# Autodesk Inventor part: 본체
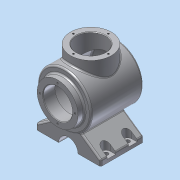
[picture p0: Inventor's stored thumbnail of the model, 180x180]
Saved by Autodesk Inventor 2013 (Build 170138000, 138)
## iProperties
Created: 2017-04
Part Number: 본체
Material: 알루미늄 6061
Document SubType Name: Modeling
Designer: narae
Density: 2.71 g/cm^3
Mass: 1670.76 g
Surface Area: 1066.88 cm^2
Volume: 616.516 cm^3
Author: narae
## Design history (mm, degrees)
sketch "스케치1"
  geometry: L1 (-50, 0)-(58, 0); L2 (-50, 0)-(-50, 50); L3 (-50, 50)-(46.336, 50); A1 r 113 centre (-55, 0) between (58, 0) and (46.336, 50); 2 further points
  constraints: 6 end point, 2 horizontal alignment, 2 perpendicular, 2 point on circle, 1 centre point, 1 horizontal, 1 midpoint, 1 point on line
  dimensions: "d0" = 108 distance of L1.end L1.start; "d1" = 50 distance of point (0, 0) L1.start; "d2" = 100 diameter of L3 L1; "d3" = 113 radius of A1
revolve "회전1" sketch "스케치1" stored, may be unused: angle "d4" = 90 deg
feature "쉘1" dims "d5" = 10
sketch "스케치2"
  geometry: C1 r 50 at (0, 0) reference; C2 r 38 at (0, 0)
  constraints: 1 centre point, 1 coincident
  dimensions: "d6" = 76 diameter of C2
extrude "돌출1" join sketch "스케치2" distance "d7" = 12; taper "d8" = 0 deg
sketch "스케치3"
  geometry: C1 r 38 at (0, 0) reference
hole "구멍1" sketch "스케치3" at (0, 0) diameter "d9" = 54; stored, may be unused: countersink angle "d13" = 90 deg, drill point angle "d15" = 0 deg; dims "d10" = 6, "d11" = 4, "d12" = 2, "d14" = 22
fillet "모깎기1" dims "d16" = 3
sketch "스케치4"
  geometry: C1 r 27 at (0, 0) reference; 1 further point
  constraints: 1 vertical alignment
  dimensions: "d17" = 32.5 distance of point (0, 32.5) C1.centre
hole "구멍2" sketch "스케치4" at (0, 32.5) diameter "d18" = 3.242; stored, may be unused: countersink angle "d22" = 90 deg, drill point angle "d24" = 118 deg; dims "d19" = 8, "d20" = 4, "d21" = 2, "d23" = 10
node "작업 평면1"
sketch "스케치5"
  geometry: C1 r 38 at (0, 0); 1 further point
  constraints: 1 centre point, 1 coincident
  dimensions: "d29" = 76 diameter of C1
extrude "돌출2" join sketch "스케치5" stored distance "d30" = 12; taper "d31" = 0 deg
sketch "스케치6"
  geometry: C1 r 38 at (0, 0) reference
hole "구멍3" sketch "스케치6" at (0, 0) diameter "d32" = 54; stored, may be unused: countersink angle "d36" = 90 deg, drill point angle "d38" = 0 deg; dims "d33" = 8, "d34" = 4, "d35" = 2, "d37" = 10
chamfer "모따기1" distance "d39" = 1; stored, may be unused: second distance "d40" = 2, angle "d41" = 45 deg
fillet "모깎기2" dims "d42" = 3
sketch "스케치7"
  geometry: C1 r 38 at (0, 0) reference; 1 further point
  constraints: 1 vertical alignment
  dimensions: "d43" = 32.5 distance of point (0, 32.5) C1.centre
hole "구멍4" sketch "스케치7" at (0, 32.5) diameter "d44" = 3.242; stored, may be unused: countersink angle "d48" = 90 deg, drill point angle "d50" = 118 deg; dims "d45" = 8, "d46" = 4, "d47" = 2, "d49" = 10
sketch "스케치8"
  geometry: L1 (-45.101, 21.584)-(-72, 60); L2 (-72, 60)-(-82, 60); L3 (-82, 60)-(-82, -60); L4 (-82, -60)-(-72, -60); L5 (-72, -60)-(-45.101, -21.584); A1 r 50 centre (0, 0) between (-45.101, 21.584) and (-45.101, -21.584) reference; 1 further point
  constraints: 10 end point, 2 equal length, 2 perpendicular, 2 point on circle, 1 horizontal
  dimensions: "d54" = 120 distance of L2.end L3.end; "d56" = 55 deg angle of L1 L2; "d58" = 10 distance of L1.end L2.end; "d59" = 82 distance from line of point (0, 0) L3; "d60" = 55 deg angle of L5 L4
extrude "돌출3" join sketch "스케치8" distance "d61" = 38; taper "d62" = 0 deg; dims "d83" = 42, "d84" = 0
sketch "스케치9"
  geometry: L1 (-60, -82)-(60, -82) reference; A1 r 18 centre (0, -82) between (18, -82) and (-18, -82); 1 further point
  constraints: 2 point on circle, 2 point on line, 1 centre point, 1 coincident, 1 midpoint
  dimensions: "d63" = 36 diameter of A1
extrude "돌출4" cut sketch "스케치9" stored distance "d64" = 80; taper "d65" = 0 deg
fillet "모깎기3" dims "d66" = 3
node "작업 평면2"
sketch "스케치10"
  geometry: L1 (-3, 42)-(-77, 42) reference; L2 (-12, 42)-(-12, 32); L3 (-28, 32)-(-28, 42); L4 (0, 0)-(0, 39) reference; A1 r 8 centre (-20, 32) between (-28, 32) and (-12, 32); 1 further point
  constraints: 4 end point, 2 perpendicular, 2 point on circle, 2 point on line, 2 tangent, 1 centre point
  dimensions: "d69" = 50 vertical distance of A1.centre point (-42, -18); "d70" = 16 distance between parallel lines of L2 L3; "d85" = 20 distance from line of A1.centre L4
extrude "돌출5" cut sketch "스케치10" stored distance "d71" = 80; taper "d72" = 0 deg
sketch "스케치11"
  geometry: A1 r 8 centre (20, -32) between (28, -32) and (12, -32) reference; 1 further point
hole "구멍5" sketch "스케치11" at (20, -32) diameter "d73" = 8; stored, may be unused: countersink angle "d77" = 90 deg, drill point angle "d79" = 0 deg; dims "d74" = 8, "d75" = 4, "d76" = 2, "d78" = 10
node "작업 평면3"
sketch "스케치12"
  geometry: 2 further points
  constraints: 1 coincident, 1 other
feature "엠보싱1" sketch "스케치12" dims "d81" = 0.5, "d82" = 0
node "솔리드1"
pattern_circular "원형 패턴1" dims angle "d26" = 360 deg
pattern_circular "원형 패턴2" dims angle "d52" = 360 deg
pattern_linear "직사각형 패턴1"
mirror "대칭3"
other parameters: "d28" = 65, "d67" = -6, "d80" = 58
